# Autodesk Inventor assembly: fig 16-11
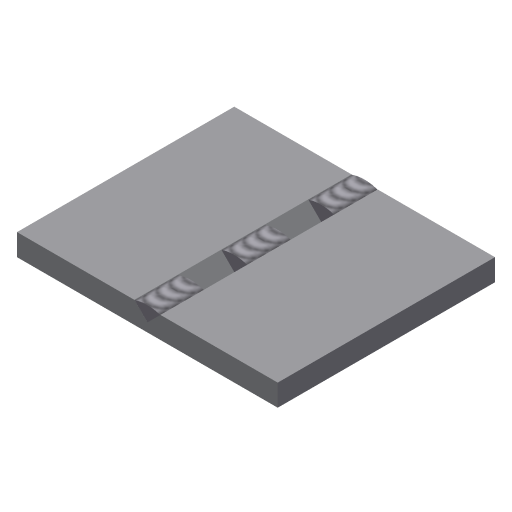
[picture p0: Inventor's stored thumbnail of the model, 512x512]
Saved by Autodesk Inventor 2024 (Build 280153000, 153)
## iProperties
Created: 2005-03
Part Number: fig 16-11
Document SubType Name: Weldment
Designer: CADCIM
Manufacturer: Standard
Standards Organization: Custom
Author: CADCIM
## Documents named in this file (2)
- D:\PROJECTS\Project 2023\RESOURCES INVENTOR 2024\RESOURCES INVENTOR 2024\Inventor_2023_Part\Inventor_2024_Part\c16_Inv_2024_prt\fig 16-11\fig 16-11.iam
- D:\PROJECTS\Project 2023\RESOURCES INVENTOR 2024\RESOURCES INVENTOR 2024\Inventor_2023_Part\Inventor_2024_Part\c16_Inv_2024_prt\fig 16-11\Part1.ipt
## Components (2 placed, 1 different names)
1. Part1:1 — Mate:1, Flush:1, Flush:2
2. Part1:2 — Mate:1, Flush:1, Flush:2
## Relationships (3: Flush 2, Mate 1)
- Mate:1: Part1:1 ↔ Part1:2
- Flush:1: Part1:1 ↔ Part1:2
- Flush:2: Part1:1 ↔ Part1:2
